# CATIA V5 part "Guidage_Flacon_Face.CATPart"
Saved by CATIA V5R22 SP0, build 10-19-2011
Part number: Guidage_Flacon_Face
Bounding box of the stored display mesh (mm): x -5 to 5, y -36 to 36, z -7.5 to 7.5
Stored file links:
  C:\Users\La forge\Desktop\CAO_PER_pick&place_2023A\Sous_Ensemble_Flacon\Guidage_Flacon_Face.CATPart
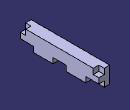
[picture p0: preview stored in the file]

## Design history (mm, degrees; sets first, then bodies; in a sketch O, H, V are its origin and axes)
Body1 (main body)
  Sketch1 on yz-plane, origin (0, 0, 0), H (0, 1, 0), V (0, 0, 1)
    line L1 (-36, 7.5) -> (36, 7.5)
    line L2 (36, 7.5) -> (36, -7.5)
    line L3 (36, -7.5) -> (-36, -7.5)
    line L4 (-36, -7.5) -> (-36, 7.5)
    length L1 = 72
    length L2 = 15
    horizontal: L1 H, L3 H
    vertical: L2 V, L4 V
    equidistance: L2 L4 O, L3 L1 O
  Pad1: profile Sketch1, direction (1, 0, 0), length 5
  Sketch2 on end face of Pad1, origin (5, 0, 0), H (0, 1, 0), V (0, 0, 1)
    point P1 (-31, 7.5)
    line L1 (-31, 7.5) -> (-36, 7.5)
    line L2 (-36, 7.5) -> (-36, 2.5)
    line L3 (-36, 2.5) -> (-31, 2.5)
    line L4 (-31, 2.5) -> (-31, 7.5)
    point P2 (-36, 7.5)
    point P3 (-36, 2.5)
    point P4 (-31, 2.5)
    reference projected line E1 (36, 7.5) -> (-36, 7.5) from edge [face of Pad1 from Sketch1.L1 | end face of Pad1]
    reference projected line E2 (-36, 7.5) -> (-36, -7.5) from edge [face of Pad1 from Sketch1.L4 | end face of Pad1]
    point P5 (-24, -7.5)
    point P6 (-36, -7.5)
    point P7 (-36, -2.5)
    point P8 (-24, -2.5)
    line L5 (-24, -7.5) -> (-36, -7.5)
    line L6 (-36, -7.5) -> (-36, -2.5)
    line L7 (-36, -2.5) -> (-24, -2.5)
    line L8 (-24, -2.5) -> (-24, -7.5)
    point P9 (-6, -7.5)
    line L9 (-6, -7.5) -> (6, -7.5)
    line L10 (6, -7.5) -> (6, -2.5)
    line L11 (6, -2.5) -> (-6, -2.5)
    line L12 (-6, -2.5) -> (-6, -7.5)
    point P13 (31, 7.5)
    point P14 (36, 7.5)
    point P15 (36, 2.5)
    point P16 (31, 2.5)
    point P17 (24, -7.5)
    point P18 (36, -7.5)
    point P19 (36, -2.5)
    point P20 (24, -2.5)
    line L13 (31, 7.5) -> (36, 7.5)
    line L14 (36, 7.5) -> (36, 2.5)
    line L15 (36, 2.5) -> (31, 2.5)
    line L16 (31, 2.5) -> (31, 7.5)
    line L17 (24, -7.5) -> (36, -7.5)
    line L18 (36, -7.5) -> (36, -2.5)
    line L19 (36, -2.5) -> (24, -2.5)
    line L20 (24, -2.5) -> (24, -7.5)
    length L4 = 5
    length L3 = 5
    length L11 = 12
    length L7 = 12
    length L8 = 5
    horizontal: L1 H, L3 H, L9 H, L11 H
    vertical: L2 V, L4 V, L10 V, L12 V
    coincidence: L1 E1, L2 E2, P9 L5, L11 L7
    symmetry: P2 P6 H, P3 P7 H, L1 L5 H, L2 L6 H, P1 P13 V, P2 P14 V, P3 P15 V, P4 P16 V, P5 P17 V, P6 P18 V, P7 P19 V, P8 P20 V, L1 L13 V, L2 L14 V, L3 L15 V, L4 L16 V, L5 L17 V, L6 L18 V, L7 L19 V, L8 L20 V
    equidistance: L12 L10 O
  Pocket1: profile Sketch2, direction (-1, 0, 0), through (limit type 6)
  Pad2: profile Sketch1, direction (-1, 0, 0), length 5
